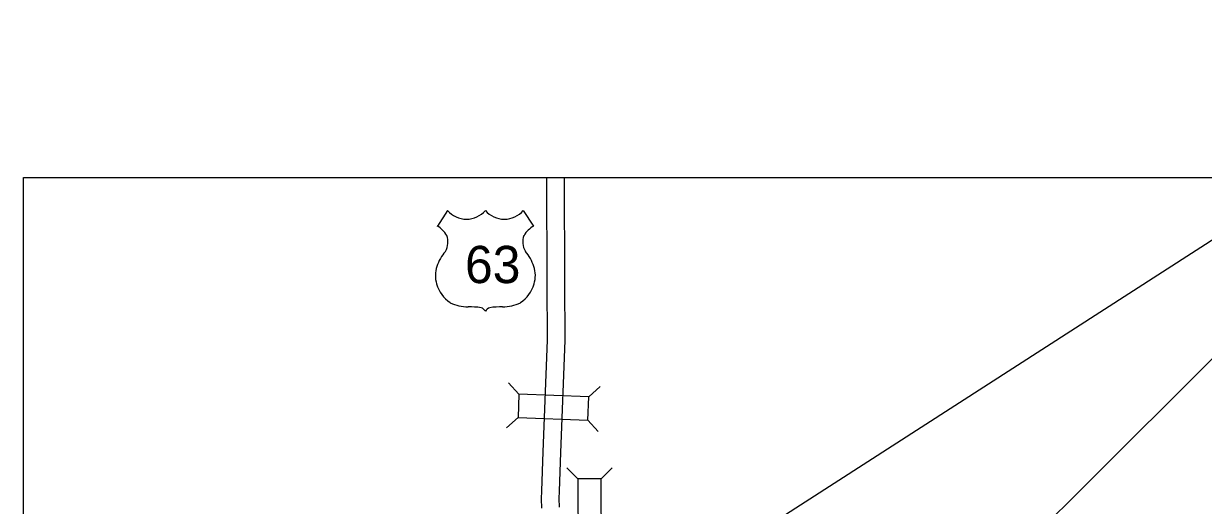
# Model space of a CAD drawing. Extents: x 982240 to 1103002, y 974866 to 1054902.
# Drawn here: x 984683 to 999731, y 1047369 to 1053520 of the extents above; entities that cross this region are included whole.
import ezdxf

# ---------------------------------------------------------------- set-up
doc = ezdxf.new("R2010")
doc.units = 0
for name, color, linetype in [('Level 15', 7, 'Continuous'), ('Level 20', 7, 'Continuous'), ('Level 22', 7, 'Continuous'), ('R_Draft', 7, 'Continuous')]:
    doc.layers.add(name, color=color, linetype=linetype)

msp = doc.modelspace()

# ---------------------------------------------------------------- linework, layer by layer
at = {"layer": 'Level 15'}
for points in [[(991351, 1051554), (991355, 1050211)], [(991576, 1051554), (991580, 1050212)], [(991355, 1050210), (991362, 1049479), (991304, 1048052), (991287, 1047554), (991286, 1047453), (991290, 1047335)], [(991580, 1050213), (991587, 1049475), (991529, 1048043), (991512, 1047550), (991511, 1047457), (991515, 1047346)]]:
    msp.add_lwpolyline(points, dxfattribs=at)
at = {"layer": 'Level 20'}
for p, q in [((991001, 1048790), (990867, 1048936)), ((991891, 1048754), (992037, 1048888)), ((990989, 1048493), (990843, 1048359)), ((991879, 1048457), (992013, 1048312)), ((991752, 1047709), (991612, 1047849)), ((992049, 1047710), (992189, 1047850))]:
    msp.add_line(p, q, dxfattribs=at)
for points in [[(991891, 1048754), (991001, 1048790), (990989, 1048493), (991879, 1048457)], [(992052, 1046819), (992049, 1047710), (991752, 1047709), (991755, 1046818)]]:
    msp.add_lwpolyline(points, close=True, dxfattribs=at)
at = {"layer": 'Level 22'}
for p, q in [((990090, 1051135), (989960, 1050935)), ((991055, 1051135), (991185, 1050935))]:
    msp.add_line(p, q, dxfattribs=at)
for centre, radius, start, end in [((990332, 1051339), 316, 220.075, 319.6701), ((990814, 1051339), 316, 220.3299, 319.925), ((989791, 1050643), 337, 30.7809, 59.9883), ((989865, 1050732), 231, 328.8105, 21.2108), ((991280, 1050732), 231, 158.7892, 211.1895), ((991355, 1050643), 337, 120.0117, 149.2191), ((990469, 1050258), 539, 138.9565, 162.6913), ((990676, 1050258), 539, 17.3086, 41.0435), ((990291, 1050303), 356, 160.9576, 197.3818), ((990854, 1050303), 356, 342.6181, 19.0423), ((990349, 1050304), 412, 195.1074, 237.1312), ((990796, 1050304), 412, 302.8688, 344.8926), ((990357, 1050433), 530, 244.0771, 269.5778), ((990369, 1048934), 970, 81.1941, 90.9539), ((990776, 1048934), 970, 89.0461, 98.8058), ((990788, 1050433), 530, 270.4221, 295.9229), ((990491, 1049804), 92.9, 28.0342, 72.9864), ((990655, 1049804), 92.9, 107.0136, 151.9658)]:
    msp.add_arc(centre, radius, start, end, dxfattribs=at)
at = {"layer": 'R_Draft'}
msp.add_lwpolyline([(991692, 1041115), (1004138, 1053520), (991631, 1045465)], dxfattribs=at)
msp.add_lwpolyline([(984683, 1051554), (1006582, 1051554), (1006582, 1032484), (984683, 1032484)], close=True, dxfattribs=at)

# ---------------------------------------------------------------- texts
at = {"layer": 'Level 22'}
msp.add_text('63', height=475.2, dxfattribs=at).set_placement((990313, 1050207))

doc.saveas('drawing.dxf')
